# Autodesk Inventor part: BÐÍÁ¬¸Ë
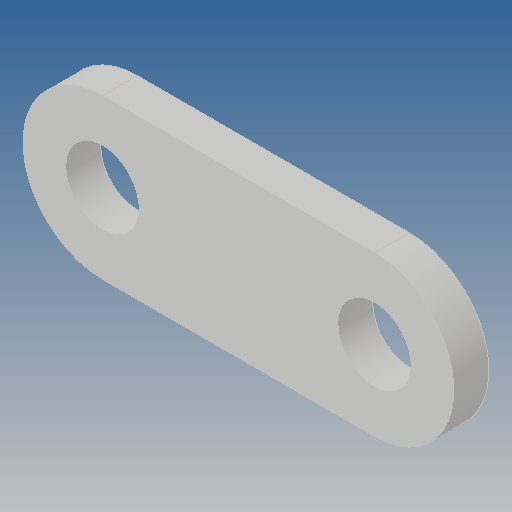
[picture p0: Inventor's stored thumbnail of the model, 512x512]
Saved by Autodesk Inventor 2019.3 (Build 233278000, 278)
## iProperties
Created: 2017-08
Part Number: BÐÍÁ¬¸Ë
Material: Ogólny
Document SubType Name: Modeling
Designer: Admin
Density: 1 g/cm^3
Appearance: Domyślna
Author: Admin
Revision Number: ÈÎºÎ
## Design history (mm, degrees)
feature "ÊäÈë1"
node "Bryła1"
